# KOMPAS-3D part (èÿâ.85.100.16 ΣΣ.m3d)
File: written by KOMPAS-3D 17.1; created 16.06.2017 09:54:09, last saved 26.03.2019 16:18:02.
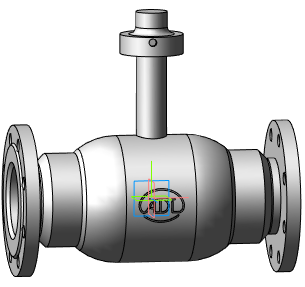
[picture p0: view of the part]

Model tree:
1. Операция без истории:2  (labels: Сталь 20  ГОСТ 1050-88)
